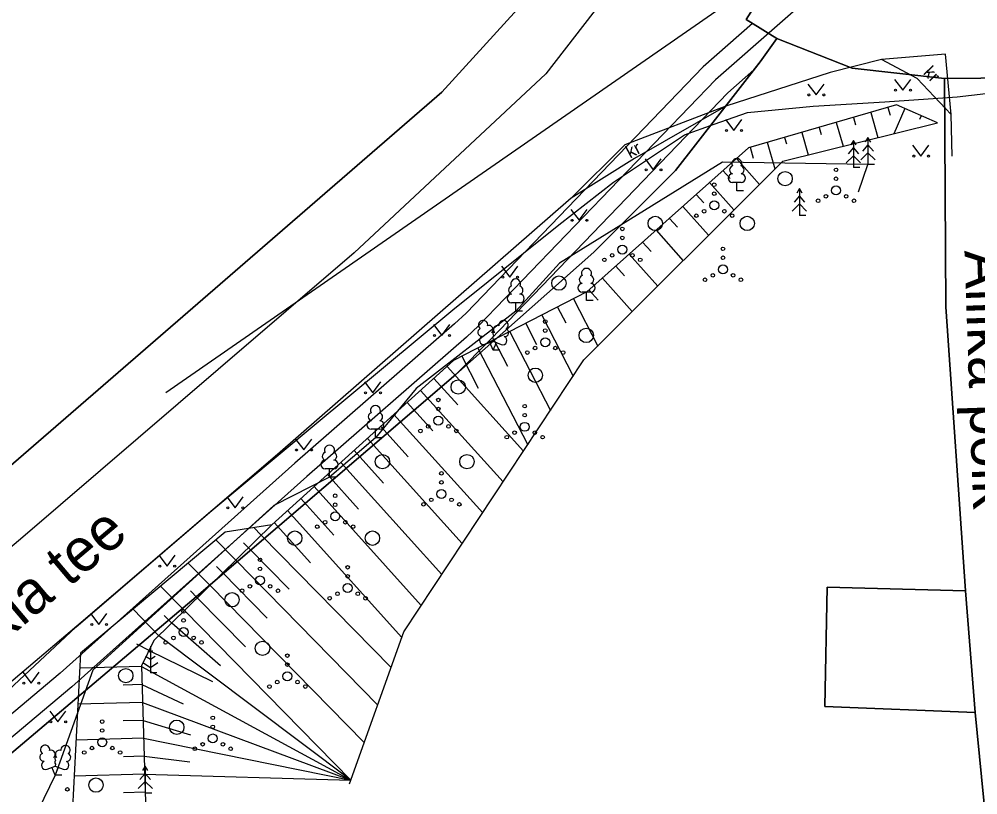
# Model space of a CAD drawing. Extents: x 648017 to 648227, y 6561313 to 6561610.
# Drawn here: x 648138.8 to 648192.3, y 6561467.4 to 6561510.6 of the extents above; entities that cross this region are included whole.
import ezdxf

# ---------------------------------------------------------------- set-up
doc = ezdxf.new("R2010")
doc.units = 0
for name, color, linetype in [('HALJASTUS', 7, 'Continuous'), ('KASUTUSALA', 7, 'Continuous'), ('KPOHULIIN', 7, 'Continuous'), ('PIIR', 7, 'Continuous'), ('PR_SIDE', 7, 'Continuous'), ('PUU', 7, 'Continuous'), ('RELJEEF', 7, 'Continuous'), ('SITRASS', 7, 'Continuous'), ('TEE', 7, 'Continuous')]:
    doc.layers.add(name, color=color, linetype=linetype)

msp = doc.modelspace()

# ---------------------------------------------------------------- linework, layer by layer
at = {"layer": 'HALJASTUS'}
for p, q in [((648182.802, 6561507.025), (648183.265, 6561506.418)), ((648183.265, 6561506.418), (648183.711, 6561507.025)), ((648187.634, 6561507.289), (648188.097, 6561506.683)), ((648188.097, 6561506.683), (648188.543, 6561507.289)), ((648178.21, 6561505.047), (648178.673, 6561504.44)), ((648178.673, 6561504.44), (648179.119, 6561505.047)), ((648188.645, 6561503.623), (648189.108, 6561503.016)), ((648189.108, 6561503.016), (648189.554, 6561503.623)), ((648173.726, 6561502.859), (648174.189, 6561502.252)), ((648174.189, 6561502.252), (648174.635, 6561502.859)), ((648169.597, 6561500.038), (648170.061, 6561499.432)), ((648170.061, 6561499.432), (648170.506, 6561500.038)), ((648165.733, 6561496.874), (648166.196, 6561496.267)), ((648166.196, 6561496.267), (648166.642, 6561496.874)), ((648161.933, 6561493.625), (648162.396, 6561493.018)), ((648162.396, 6561493.018), (648162.842, 6561493.625)), ((648158.085, 6561490.432), (648158.548, 6561489.826)), ((648158.548, 6561489.826), (648158.994, 6561490.432)), ((648154.236, 6561487.24), (648154.7, 6561486.633)), ((648154.7, 6561486.633), (648155.145, 6561487.24)), ((648150.409, 6561484.023), (648150.872, 6561483.416)), ((648150.872, 6561483.416), (648151.318, 6561484.023)), ((648146.613, 6561480.769), (648147.076, 6561480.162)), ((648147.076, 6561480.162), (648147.522, 6561480.769)), ((648142.817, 6561477.514), (648143.28, 6561476.908)), ((648143.28, 6561476.908), (648143.726, 6561477.514)), ((648139.035, 6561474.244), (648139.498, 6561473.637)), ((648139.498, 6561473.637), (648139.944, 6561474.244)), ((648140.535, 6561472.085), (648140.998, 6561471.478)), ((648140.998, 6561471.478), (648141.444, 6561472.085))]:
    msp.add_line(p, q, dxfattribs=at)
msp.add_lwpolyline([(648185.624, 6561501.029), (648186.158, 6561502.545), (648178.048, 6561502.668), (648168.965, 6561497.048), (648166.518, 6561494.366), (648160.96, 6561490.067), (648158.695, 6561487.313), (648156.134, 6561485.11), (648153.031, 6561483.538), (648142.942, 6561474.365), (648140.838, 6561468.512), (648139.267, 6561465.252), (648137.737, 6561460.573), (648130.77, 6561454.441), (648126.403, 6561456.396), (648120.992, 6561455.337), (648118.741, 6561454.027), (648113.276, 6561447.469), (648113.195, 6561446.44), (648114.768, 6561444.874), (648116.607, 6561441.073)], dxfattribs=at)
for centre, radius in [((648182.864, 6561506.418), 0.055), ((648183.693, 6561506.418), 0.055), ((648187.696, 6561506.683), 0.055), ((648188.525, 6561506.683), 0.055), ((648178.272, 6561504.44), 0.055), ((648179.101, 6561504.44), 0.055), ((648188.707, 6561503.016), 0.055), ((648189.536, 6561503.016), 0.055), ((648173.788, 6561502.252), 0.055), ((648174.617, 6561502.252), 0.055), ((648181.535, 6561501.756), 0.4), ((648184.376, 6561502.247), 0.1), ((648177.586, 6561501.415), 0.1), ((648184.376, 6561501.747), 0.1), ((648177.586, 6561500.915), 0.1), ((648184.376, 6561501.097), 0.25), ((648177.586, 6561500.265), 0.25), ((648183.376, 6561500.522), 0.1), ((648183.811, 6561500.772), 0.1), ((648184.941, 6561500.772), 0.1), ((648185.376, 6561500.522), 0.1), ((648177.021, 6561499.94), 0.1), ((648178.151, 6561499.94), 0.1), ((648169.66, 6561499.432), 0.055), ((648170.488, 6561499.432), 0.055), ((648174.295, 6561499.26), 0.4), ((648176.586, 6561499.69), 0.1), ((648178.586, 6561499.69), 0.1), ((648179.422, 6561499.26), 0.4), ((648172.459, 6561498.954), 0.1), ((648172.459, 6561498.454), 0.1), ((648172.459, 6561497.804), 0.25), ((648178.071, 6561497.845), 0.1), ((648171.459, 6561497.229), 0.1), ((648171.894, 6561497.479), 0.1), ((648173.024, 6561497.479), 0.1), ((648173.459, 6561497.229), 0.1), ((648178.071, 6561497.345), 0.1), ((648178.071, 6561496.695), 0.25), ((648165.795, 6561496.267), 0.055), ((648166.624, 6561496.267), 0.055), ((648168.925, 6561495.932), 0.4), ((648177.071, 6561496.12), 0.1), ((648177.506, 6561496.37), 0.1), ((648178.636, 6561496.37), 0.1), ((648179.071, 6561496.12), 0.1), ((648168.163, 6561493.789), 0.1), ((648161.995, 6561493.018), 0.055), ((648162.824, 6561493.018), 0.055), ((648168.163, 6561493.289), 0.1), ((648170.449, 6561493.02), 0.4), ((648167.598, 6561492.314), 0.1), ((648168.163, 6561492.639), 0.25), ((648168.728, 6561492.314), 0.1), ((648167.163, 6561492.064), 0.1), ((648169.163, 6561492.064), 0.1), ((648167.608, 6561490.801), 0.4), ((648163.313, 6561490.143), 0.4), ((648158.147, 6561489.826), 0.055), ((648158.976, 6561489.826), 0.055), ((648162.204, 6561489.421), 0.1), ((648162.204, 6561488.921), 0.1), ((648167.019, 6561489.074), 0.1), ((648167.019, 6561488.574), 0.1), ((648162.204, 6561488.271), 0.25), ((648167.019, 6561487.924), 0.25), ((648161.204, 6561487.696), 0.1), ((648161.639, 6561487.946), 0.1), ((648162.769, 6561487.946), 0.1), ((648163.204, 6561487.696), 0.1), ((648166.454, 6561487.599), 0.1), ((648167.584, 6561487.599), 0.1), ((648166.019, 6561487.349), 0.1), ((648168.019, 6561487.349), 0.1), ((648154.299, 6561486.633), 0.055), ((648155.127, 6561486.633), 0.055), ((648159.086, 6561485.983), 0.4), ((648163.798, 6561485.983), 0.4), ((648162.377, 6561485.33), 0.1), ((648162.377, 6561484.83), 0.1), ((648162.377, 6561484.18), 0.25), ((648156.453, 6561484.082), 0.1), ((648161.812, 6561483.855), 0.1), ((648162.942, 6561483.855), 0.1), ((648150.471, 6561483.416), 0.055), ((648151.3, 6561483.416), 0.055), ((648156.453, 6561483.582), 0.1), ((648161.377, 6561483.605), 0.1), ((648163.377, 6561483.605), 0.1), ((648156.453, 6561482.932), 0.25), ((648155.453, 6561482.357), 0.1), ((648155.888, 6561482.607), 0.1), ((648157.018, 6561482.607), 0.1), ((648157.453, 6561482.357), 0.1), ((648154.201, 6561481.719), 0.4), ((648158.532, 6561481.719), 0.4), ((648146.675, 6561480.162), 0.055), ((648147.504, 6561480.162), 0.055), ((648152.261, 6561480.512), 0.1), ((648152.261, 6561480.012), 0.1), ((648157.146, 6561480.096), 0.1), ((648152.261, 6561479.362), 0.25), ((648157.146, 6561479.596), 0.1), ((648151.696, 6561479.037), 0.1), ((648152.826, 6561479.037), 0.1), ((648157.146, 6561478.946), 0.25), ((648150.702, 6561478.287), 0.4), ((648151.261, 6561478.787), 0.1), ((648153.261, 6561478.787), 0.1), ((648156.581, 6561478.621), 0.1), ((648157.711, 6561478.621), 0.1), ((648156.146, 6561478.371), 0.1), ((648158.146, 6561478.371), 0.1), ((648148, 6561477.635), 0.1), ((648142.879, 6561476.908), 0.055), ((648143.708, 6561476.908), 0.055), ((648148, 6561477.135), 0.1), ((648148, 6561476.485), 0.25), ((648147, 6561475.91), 0.1), ((648147.435, 6561476.16), 0.1), ((648148.565, 6561476.16), 0.1), ((648149, 6561475.91), 0.1), ((648152.4, 6561475.583), 0.4), ((648153.785, 6561475.173), 0.1), ((648153.785, 6561474.673), 0.1), ((648144.778, 6561474.058), 0.4), ((648153.785, 6561474.023), 0.25), ((648139.097, 6561473.637), 0.055), ((648139.926, 6561473.637), 0.055), ((648153.22, 6561473.698), 0.1), ((648154.35, 6561473.698), 0.1), ((648152.785, 6561473.448), 0.1), ((648154.785, 6561473.448), 0.1), ((648143.462, 6561471.499), 0.1), ((648147.619, 6561471.181), 0.4), ((648149.628, 6561471.707), 0.1), ((648140.597, 6561471.478), 0.055), ((648141.426, 6561471.478), 0.055), ((648143.462, 6561470.999), 0.1), ((648149.628, 6561471.207), 0.1), ((648143.462, 6561470.349), 0.25), ((648149.628, 6561470.557), 0.25), ((648142.897, 6561470.024), 0.1), ((648144.027, 6561470.024), 0.1), ((648148.628, 6561469.982), 0.1), ((648149.063, 6561470.232), 0.1), ((648150.193, 6561470.232), 0.1), ((648150.628, 6561469.982), 0.1), ((648142.462, 6561469.774), 0.1), ((648144.462, 6561469.774), 0.1), ((648143.115, 6561467.957), 0.4), ((648141.522, 6561467.72), 0.1)]:
    msp.add_circle(centre, radius, dxfattribs=at)
at = {"layer": 'KASUTUSALA'}
msp.add_lwpolyline([(648069.33, 6561411.95), (648079.41, 6561420.36), (648130.76, 6561463.29), (648148.46, 6561478.24), (648152.687, 6561481.861), (648163.17, 6561490.84), (648165.149, 6561492.835), (648178.343, 6561506.54), (648179.793, 6561507.812), (648180.15, 6561508.27), (648181.07, 6561509.57), (648179.717, 6561510.405), (648176.961, 6561507.989), (648163.749, 6561494.265), (648163.1, 6561493.666), (648154.204, 6561485.901), (648141.111, 6561474.192), (648118.068, 6561454.823), (648078.72, 6561421.738), (648068.502, 6561412.945), (648066.261, 6561409.593)], close=True, dxfattribs=at)
at = {"layer": 'KPOHULIIN'}
msp.add_lwpolyline([(648203.378, 6561528.855), (648192.767, 6561521.546), (648147.002, 6561489.823)], dxfattribs=at)
at = {"layer": 'PIIR'}
for points in [[(648199.342, 6561559.885), (648199.07, 6561558.2), (648195.16, 6561543.45), (648190.37, 6561530.46), (648184.89, 6561519.28), (648179.37, 6561510.62), (648181.07, 6561509.57), (648180.15, 6561508.27), (648175.42, 6561502.2), (648170.88, 6561497.65), (648163.17, 6561490.84), (648148.46, 6561478.24), (648130.76, 6561463.29), (648079.41, 6561420.36), (648069.33, 6561411.95), (648039.275, 6561388.867)], [(648039.275, 6561403.329), (648123.09, 6561472.56), (648162.4, 6561506.57), (648170.84, 6561515.84), (648172.53, 6561514.72), (648177.65, 6561522.71), (648182.83, 6561533.2), (648187.47, 6561545.71), (648191.21, 6561559.62), (648191.239, 6561559.885)], [(648191.239, 6561559.885), (648191.21, 6561559.62), (648187.47, 6561545.71), (648182.83, 6561533.2), (648177.65, 6561522.71), (648172.53, 6561514.72), (648170.84, 6561515.84), (648162.4, 6561506.57), (648123.09, 6561472.56), (648090, 6561513.15), (648148.783, 6561559.885)], [(648204.275, 6561507.585), (648196.49, 6561507.4), (648190.43, 6561507.33), (648185.28, 6561507.91), (648181.07, 6561509.57), (648179.37, 6561510.62), (648184.89, 6561519.28), (648190.37, 6561530.46), (648195.16, 6561543.45), (648199.07, 6561558.2), (648199.342, 6561559.885)], [(648128.277, 6561349.885), (648122.86, 6561391.28), (648138.52, 6561393.32), (648130.76, 6561463.29), (648148.46, 6561478.24), (648163.17, 6561490.84), (648170.88, 6561497.65), (648175.42, 6561502.2), (648180.15, 6561508.27), (648181.07, 6561509.57), (648185.28, 6561507.91), (648190.43, 6561507.33), (648190.49, 6561494.61), (648191.59, 6561478.79), (648183.88, 6561478.99), (648183.75, 6561472.33), (648192.14, 6561472), (648192.72, 6561465.96), (648194.12, 6561456.75), (648195.36, 6561449.36), (648197.34, 6561442.54), (648200.74, 6561433.7), (648204.275, 6561426.345)], [(648204.275, 6561426.345), (648200.74, 6561433.7), (648197.34, 6561442.54), (648195.36, 6561449.36), (648194.12, 6561456.75), (648192.72, 6561465.96), (648192.14, 6561472), (648191.59, 6561478.79), (648190.49, 6561494.61), (648190.43, 6561507.33), (648196.49, 6561507.4), (648198.03, 6561474.9), (648200.68, 6561456.78), (648204.275, 6561443.421)]]:
    msp.add_lwpolyline(points, dxfattribs=at)
msp.add_lwpolyline([(648183.75, 6561472.33), (648183.88, 6561478.99), (648191.59, 6561478.79), (648192.14, 6561472)], close=True, dxfattribs=at)
at = {"layer": 'PR_SIDE'}
msp.add_lwpolyline([(648199.292, 6561518.475), (648197.479, 6561519.53), (648193.724, 6561520.506), (648191.997, 6561519.841), (648177.652, 6561507.265), (648164.449, 6561493.55), (648163.768, 6561492.922), (648154.867, 6561485.151), (648141.766, 6561473.436), (648118.712, 6561454.058), (648079.383, 6561420.989), (648069.186, 6561412.213), (648060.526, 6561403.421), (648044.656, 6561390.621), (648039.275, 6561386.529)], dxfattribs=at)
at = {"layer": 'PUU'}
for p, q in [((648185.348, 6561503.885), (648185.198, 6561503.635)), ((648185.498, 6561503.635), (648185.348, 6561503.885)), ((648185.348, 6561503.885), (648185.348, 6561502.385)), ((648186.158, 6561503.645), (648185.858, 6561503.295)), ((648186.158, 6561504.045), (648186.008, 6561503.795)), ((648186.308, 6561503.795), (648186.158, 6561504.045)), ((648186.158, 6561504.045), (648186.158, 6561502.545)), ((648186.458, 6561503.295), (648186.158, 6561503.645)), ((648185.348, 6561503.485), (648185.048, 6561503.135)), ((648185.648, 6561503.135), (648185.348, 6561503.485)), ((648186.158, 6561503.195), (648185.758, 6561502.795)), ((648186.558, 6561502.795), (648186.158, 6561503.195)), ((648185.348, 6561503.035), (648184.948, 6561502.635)), ((648185.748, 6561502.635), (648185.348, 6561503.035)), ((648186.518, 6561502.545), (648186.158, 6561502.545)), ((648185.708, 6561502.385), (648185.348, 6561502.385)), ((648179.086, 6561501.548), (648178.606, 6561501.548)), ((648178.846, 6561501.073), (648178.846, 6561501.548)), ((648179.226, 6561501.073), (648178.846, 6561501.073)), ((648182.336, 6561501.201), (648182.186, 6561500.951)), ((648182.486, 6561500.951), (648182.336, 6561501.201)), ((648182.336, 6561501.201), (648182.336, 6561499.701)), ((648182.336, 6561500.801), (648182.036, 6561500.451)), ((648182.636, 6561500.451), (648182.336, 6561500.801)), ((648182.336, 6561500.351), (648181.936, 6561499.951)), ((648182.736, 6561499.951), (648182.336, 6561500.351)), ((648182.696, 6561499.701), (648182.336, 6561499.701)), ((648170.704, 6561495.433), (648170.224, 6561495.433)), ((648170.464, 6561494.958), (648170.464, 6561495.433)), ((648166.758, 6561494.841), (648166.278, 6561494.841)), ((648166.518, 6561494.366), (648166.518, 6561494.841)), ((648170.844, 6561494.958), (648170.464, 6561494.958)), ((648166.898, 6561494.366), (648166.518, 6561494.366)), ((648164.817, 6561492.523), (648165.262, 6561492.698)), ((648165.257, 6561492.188), (648165.082, 6561492.628)), ((648165.257, 6561492.188), (648165.437, 6561492.628)), ((648165.262, 6561492.698), (648165.702, 6561492.518)), ((648165.637, 6561492.188), (648165.257, 6561492.188)), ((648158.935, 6561487.788), (648158.455, 6561487.788)), ((648158.695, 6561487.313), (648158.695, 6561487.788)), ((648159.075, 6561487.313), (648158.695, 6561487.313)), ((648156.374, 6561485.585), (648155.894, 6561485.585)), ((648156.134, 6561485.11), (648156.134, 6561485.585)), ((648156.514, 6561485.11), (648156.134, 6561485.11)), ((648146.149, 6561475.356), (648146.025, 6561475.439)), ((648146.149, 6561475.706), (648146.149, 6561474.206)), ((648146.273, 6561475.439), (648146.149, 6561475.356)), ((648145.725, 6561474.796), (648146.149, 6561474.513)), ((648146.149, 6561474.956), (648145.882, 6561475.134)), ((648146.416, 6561475.134), (648146.149, 6561474.956)), ((648146.149, 6561474.513), (648146.573, 6561474.796)), ((648146.509, 6561474.206), (648146.149, 6561474.206)), ((648140.398, 6561468.847), (648140.843, 6561469.022)), ((648140.838, 6561468.512), (648140.663, 6561468.952)), ((648140.838, 6561468.512), (648141.018, 6561468.952)), ((648140.843, 6561469.022), (648141.283, 6561468.842)), ((648145.863, 6561469.013), (648145.713, 6561468.763)), ((648146.013, 6561468.763), (648145.863, 6561469.013)), ((648145.863, 6561469.013), (648145.863, 6561467.513)), ((648141.218, 6561468.512), (648140.838, 6561468.512)), ((648145.863, 6561468.613), (648145.563, 6561468.263)), ((648146.163, 6561468.263), (648145.863, 6561468.613)), ((648145.863, 6561468.163), (648145.463, 6561467.763)), ((648146.263, 6561467.763), (648145.863, 6561468.163)), ((648146.223, 6561467.513), (648145.863, 6561467.513))]:
    msp.add_line(p, q, dxfattribs=at)
for points in [[(648165.262, 6561493.193), (648165.242, 6561493.118), (648165.242, 6561493.098), (648165.252, 6561493.068), (648165.272, 6561493.033), (648165.277, 6561493.013), (648165.262, 6561492.978), (648165.237, 6561492.928), (648165.232, 6561492.903), (648165.237, 6561492.888), (648165.247, 6561492.858), (648165.282, 6561492.798), (648165.287, 6561492.778), (648165.282, 6561492.758), (648165.267, 6561492.723), (648165.262, 6561492.698)], [(648140.843, 6561469.517), (648140.823, 6561469.442), (648140.823, 6561469.422), (648140.833, 6561469.392), (648140.853, 6561469.357), (648140.858, 6561469.337), (648140.843, 6561469.302), (648140.818, 6561469.252), (648140.813, 6561469.227), (648140.818, 6561469.212), (648140.828, 6561469.182), (648140.863, 6561469.122), (648140.868, 6561469.102), (648140.863, 6561469.082), (648140.848, 6561469.047), (648140.843, 6561469.022)]]:
    msp.add_lwpolyline(points, dxfattribs=at)
for centre, radius, start, end in [((648178.846, 6561502.593), 0.277, 332.5799, 207.4201), ((648178.609, 6561501.785), 0.238, 90.0016, 269.3953), ((648178.676, 6561502.245), 0.233, 109.0217, 253.1415), ((648179.016, 6561502.245), 0.233, 286.8508, 70.9859), ((648179.083, 6561501.785), 0.238, 270.6047, 89.9984), ((648170.464, 6561496.478), 0.277, 332.5799, 207.4201), ((648166.518, 6561495.886), 0.277, 332.5799, 207.4201), ((648170.294, 6561496.131), 0.233, 109.0217, 253.1415), ((648170.634, 6561496.131), 0.233, 286.8508, 70.9859), ((648166.348, 6561495.538), 0.233, 109.0217, 253.1415), ((648166.688, 6561495.538), 0.233, 286.8508, 70.9859), ((648170.227, 6561495.671), 0.238, 90.0016, 269.3953), ((648170.702, 6561495.671), 0.238, 270.6047, 89.9984), ((648166.281, 6561495.078), 0.238, 90.0016, 269.3953), ((648166.756, 6561495.078), 0.238, 270.6047, 89.9984), ((648164.7, 6561493.602), 0.256, 111.5027, 232.5173), ((648164.7, 6561493.602), 0.256, 350.4856, 111.5002), ((648165.034, 6561493.351), 0.224, 308.5041, 111.5725), ((648165.497, 6561493.347), 0.225, 67.7016, 230.5126), ((648165.836, 6561493.593), 0.256, 67.6168, 188.6314), ((648165.836, 6561493.593), 0.256, 306.5997, 67.6143), ((648164.626, 6561493.191), 0.224, 111.4304, 274.4987), ((648164.73, 6561492.746), 0.237, 111.5014, 291.5004), ((648165.261, 6561492.955), 0.237, 66.7655, 111.5015), ((648165.792, 6561492.738), 0.237, 247.6166, 67.6155), ((648165.903, 6561493.181), 0.224, 264.6183, 67.6866), ((648158.525, 6561488.485), 0.233, 109.0217, 253.1415), ((648158.695, 6561488.833), 0.277, 332.5799, 207.4201), ((648158.865, 6561488.485), 0.233, 286.8508, 70.9859), ((648158.458, 6561488.025), 0.238, 90.0016, 269.3953), ((648158.933, 6561488.025), 0.238, 270.6047, 89.9984), ((648156.134, 6561486.63), 0.277, 332.5799, 207.4201), ((648155.897, 6561485.822), 0.238, 90.0016, 269.3953), ((648155.964, 6561486.283), 0.233, 109.0217, 253.1415), ((648156.304, 6561486.283), 0.233, 286.8508, 70.9859), ((648156.372, 6561485.822), 0.238, 270.6047, 89.9984), ((648140.281, 6561469.926), 0.256, 111.5027, 232.5173), ((648140.281, 6561469.926), 0.256, 350.4856, 111.5002), ((648141.417, 6561469.917), 0.256, 67.6168, 188.6314), ((648141.417, 6561469.917), 0.256, 306.5997, 67.6143), ((648140.207, 6561469.515), 0.224, 111.4304, 274.4987), ((648140.616, 6561469.676), 0.224, 308.5041, 111.5725), ((648140.842, 6561469.279), 0.237, 66.7655, 111.5015), ((648141.079, 6561469.671), 0.225, 67.7016, 230.5126), ((648141.485, 6561469.505), 0.224, 264.6183, 67.6866), ((648140.312, 6561469.07), 0.237, 111.5014, 291.5004), ((648141.373, 6561469.062), 0.237, 247.6166, 67.6155)]:
    msp.add_arc(centre, radius, start, end, dxfattribs=at)
at = {"layer": 'RELJEEF'}
for p, q in [((648186.309, 6561505.443), (648186.715, 6561504.04)), ((648187.27, 6561505.721), (648187.395, 6561505.288)), ((648188.209, 6561505.66), (648187.595, 6561504.257)), ((648189.125, 6561505.259), (648189.033, 6561505.049)), ((648184.388, 6561504.889), (648184.771, 6561503.561)), ((648185.349, 6561505.166), (648185.467, 6561504.756)), ((648182.466, 6561504.334), (648182.828, 6561503.083)), ((648183.427, 6561504.611), (648183.539, 6561504.224)), ((648180.545, 6561503.779), (648180.973, 6561502.297)), ((648181.506, 6561504.056), (648181.611, 6561503.692)), ((648179.584, 6561503.501), (648179.758, 6561502.898)), ((648178.819, 6561502.869), (648180.104, 6561501.429)), ((648178.073, 6561502.204), (648178.47, 6561501.759)), ((648177.327, 6561501.538), (648178.687, 6561500.013)), ((648176.581, 6561500.872), (648177, 6561500.402)), ((648175.834, 6561500.207), (648177.27, 6561498.597)), ((648175.088, 6561499.541), (648175.53, 6561499.046)), ((648174.342, 6561498.875), (648175.853, 6561497.181)), ((648173.595, 6561498.21), (648174.06, 6561497.689)), ((648172.849, 6561497.544), (648174.436, 6561495.765)), ((648172.103, 6561496.878), (648172.59, 6561496.332)), ((648171.357, 6561496.213), (648173.019, 6561494.349)), ((648170.61, 6561495.547), (648171.121, 6561494.975)), ((648168.855, 6561494.599), (648169.305, 6561493.725)), ((648169.744, 6561495.056), (648171.097, 6561492.428)), ((648167.966, 6561494.141), (648169.716, 6561490.739)), ((648167.077, 6561493.684), (648167.679, 6561492.514)), ((648166.187, 6561493.226), (648168.45, 6561488.828)), ((648165.298, 6561492.769), (648166.054, 6561491.3)), ((648163.52, 6561491.854), (648164.429, 6561490.086)), ((648164.409, 6561492.311), (648167.184, 6561486.918)), ((648162.7, 6561491.295), (648166.958, 6561486.577)), ((648161.958, 6561490.625), (648163.287, 6561489.153)), ((648161.215, 6561489.955), (648165.817, 6561484.856)), ((648160.473, 6561489.285), (648161.905, 6561487.698)), ((648159.731, 6561488.616), (648164.677, 6561483.135)), ((648158.988, 6561487.946), (648160.524, 6561486.244)), ((648158.246, 6561487.276), (648163.536, 6561481.414)), ((648157.503, 6561486.606), (648159.142, 6561484.79)), ((648156.761, 6561485.936), (648162.395, 6561479.693)), ((648156.019, 6561485.266), (648157.761, 6561483.336)), ((648155.276, 6561484.596), (648161.255, 6561477.971)), ((648154.534, 6561483.926), (648156.379, 6561481.881)), ((648153.792, 6561483.256), (648160.168, 6561476.191)), ((648152.331, 6561481.89), (648151.919, 6561482.31)), ((648153.049, 6561482.586), (648155.07, 6561480.346)), ((648152.331, 6561481.89), (648159.57, 6561474.516)), ((648150.904, 6561480.489), (648149.795, 6561481.619)), ((648151.617, 6561481.19), (648151.345, 6561481.467)), ((648151.617, 6561481.19), (648153.891, 6561478.874)), ((648149.476, 6561479.088), (648148.257, 6561480.33)), ((648150.19, 6561479.789), (648149.841, 6561480.144)), ((648150.904, 6561480.489), (648158.824, 6561472.422)), ((648150.19, 6561479.789), (648152.668, 6561477.265)), ((648148.049, 6561477.687), (648146.719, 6561479.042)), ((648149.476, 6561479.088), (648158.077, 6561470.328)), ((648148.763, 6561478.387), (648148.38, 6561478.777)), ((648148.763, 6561478.387), (648151.445, 6561475.656)), ((648146.622, 6561476.286), (648145.181, 6561477.754)), ((648148.049, 6561477.687), (648157.33, 6561468.234)), ((648147.336, 6561476.986), (648146.92, 6561477.41)), ((648150.054, 6561474.599), (648147.336, 6561476.986)), ((648157.33, 6561468.234), (648146.622, 6561476.286)), ((648146.073, 6561475.466), (648145.389, 6561475.804)), ((648146.073, 6561475.466), (648149.603, 6561473.726)), ((648145.653, 6561474.565), (648142.214, 6561474.466)), ((648145.653, 6561474.565), (648157.33, 6561468.234)), ((648145.681, 6561473.565), (648144.625, 6561473.535)), ((648145.681, 6561473.565), (648147.968, 6561472.494)), ((648145.71, 6561472.565), (648142.108, 6561472.462)), ((648145.71, 6561472.565), (648157.33, 6561468.234)), ((648145.739, 6561471.566), (648144.634, 6561471.534)), ((648145.739, 6561471.566), (648148.386, 6561470.751)), ((648145.768, 6561470.566), (648142.002, 6561470.458)), ((648145.768, 6561470.566), (648157.33, 6561468.234)), ((648145.796, 6561469.567), (648144.642, 6561469.533)), ((648145.796, 6561469.567), (648148.352, 6561469.246)), ((648145.825, 6561468.567), (648141.896, 6561468.454)), ((648145.825, 6561468.567), (648157.33, 6561468.234)), ((648145.854, 6561467.567), (648144.651, 6561467.533))]:
    msp.add_line(p, q, dxfattribs=at)
for points in [[(648190.041, 6561504.859), (648187.751, 6561505.86), (648179.501, 6561503.477), (648170.491, 6561495.441), (648163.052, 6561491.613), (648152.922, 6561482.471), (648146.341, 6561476.01), (648145.651, 6561474.611), (648145.943, 6561464.469)], [(648157.258, 6561468.032), (648160.276, 6561476.495), (648170.324, 6561491.655), (648181.409, 6561502.734), (648190.041, 6561504.859)], [(648152.922, 6561482.471), (648150.31, 6561482.05), (648142.259, 6561475.306), (648141.689, 6561464.543)]]:
    msp.add_lwpolyline(points, dxfattribs=at)
at = {"layer": 'SITRASS'}
msp.add_lwpolyline([(648135.65, 6561470.85), (648142, 6561476.76), (648149.47, 6561483.17), (648155.28, 6561488.02), (648163.02, 6561494.44), (648168.93, 6561499.19), (648171.97, 6561501.56), (648175.043, 6561503.606), (648175.92, 6561504.19), (648177.581, 6561504.785), (648179.44, 6561505.45), (648183.1, 6561505.79), (648187.09, 6561506.04), (648191.13, 6561506.32), (648202.808, 6561507.679), (648204.275, 6561507.849)], dxfattribs=at)
at = {"layer": 'TEE'}
for points in [[(648180.645, 6561526.052), (648175.165, 6561516.611), (648168.192, 6561507.6), (648157.516, 6561497.617), (648149.936, 6561491.11), (648138.911, 6561481.662), (648130.582, 6561474.696), (648128.755, 6561474.385)], [(648190.847, 6561503.014), (648190.795, 6561505.329), (648190.473, 6561508.69), (648186.913, 6561508.391), (648184.052, 6561507.669), (648178.235, 6561505.797), (648172.597, 6561503.638), (648169.601, 6561500.659), (648161.13, 6561493.277), (648153.241, 6561486.387), (648142.295, 6561477.024), (648134.213, 6561470.18), (648127.303, 6561464.531), (648121.652, 6561459.668), (648108.949, 6561448.834), (648091.715, 6561434.542), (648078.474, 6561423.42), (648076.859, 6561419.217), (648076.802, 6561415.34), (648077.814, 6561412.283), (648079.886, 6561408.026), (648080.807, 6561407.116)], [(648190.795, 6561505.329), (648188.897, 6561507.336), (648186.913, 6561508.391)], [(648178.235, 6561505.797), (648173.131, 6561502.883), (648169.601, 6561500.659)]]:
    msp.add_lwpolyline(points, dxfattribs=at)

# ---------------------------------------------------------------- texts
at = {"layer": 'PIIR'}
for s, rotation, p in [('Allika põik', 271.9547, (648191.534, 6561497.741)), ('17101 Roela-Rahkla tee', 40.1668, (648118.556, 6561459.507))]:
    msp.add_text(s, height=2.4, rotation=rotation, dxfattribs=at).set_placement(p)
at = {"layer": 'TEE'}
for rotation, p in [(313.7161, (648189.2, 6561507.626)), (28.2492, (648172.893, 6561502.87))]:
    msp.add_text('kr', height=0.7, rotation=rotation, dxfattribs=at).set_placement(p)

doc.saveas('drawing.dxf')
